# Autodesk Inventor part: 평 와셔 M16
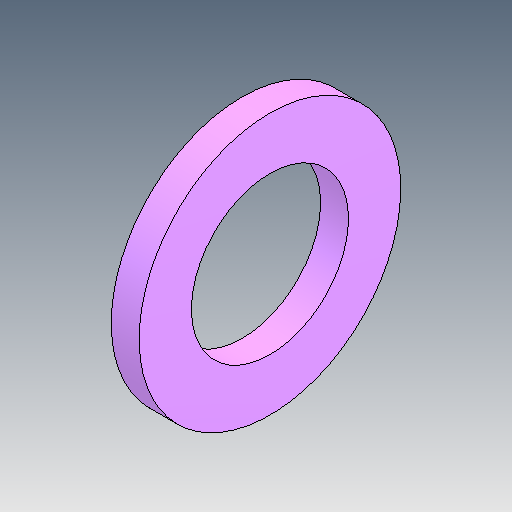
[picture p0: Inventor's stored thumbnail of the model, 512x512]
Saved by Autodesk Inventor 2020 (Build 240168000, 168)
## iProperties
Created: 2025-01
Part Number: 평 와셔 M16
Material: 강철, 연강
Description: 평면 와셔
Document SubType Name: Modeling
Designer: 1강의실14
Density: 7.85 g/cm^3
Appearance: 기본값
Author: jhkim
Sending System: Autodesk Inventor 2025
Preprocessor: ST-DEVELOPER v20
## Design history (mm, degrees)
feature "Solid1"
node "솔리드1"
